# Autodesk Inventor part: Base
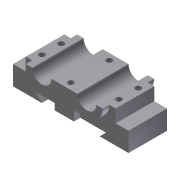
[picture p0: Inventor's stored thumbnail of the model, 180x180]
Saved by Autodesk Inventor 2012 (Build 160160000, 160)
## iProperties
Shininess: 77.0
Length Units: 11269
Angle Units: 11279
Time Units: 11290
Mass Units: 11283
Length Display Precision: 3
Angle Display Precision: 2
Created: 2002-02
Part Number: Base
Document SubType Name: Modeling
Designer: ***
Density: 1 g/cm^3
Material: Default
Density: 0.0
Volumn: 0.0
Area: 0.0
PropertySet Name: Model Information
Control State: 0
Master: False
Checked Out: False
Author: ***
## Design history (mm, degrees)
sketch "Sketch2"
  geometry: L1 (-10.066, -1.263)-(24.934, -1.263); L2 (37.434, 11.237)-(32.434, 11.237); L3 (17.434, 11.237)-(-2.566, 11.237); L4 (-17.566, 11.237)-(-22.566, 11.237); A1 r 12.5 centre (-10.066, 11.237) between (-22.566, 11.237) and (-10.066, -1.263); A2 r 12.5 centre (24.934, 11.237) between (24.934, -1.263) and (37.434, 11.237); A3 r 7.5 centre (24.934, 11.237) between (17.434, 11.237) and (32.434, 11.237); A4 r 7.5 centre (-10.066, 11.237) between (-17.566, 11.237) and (-2.566, 11.237)
  constraints: 8 end point, 8 point on circle, 4 centre point, 3 horizontal, 3 parallel, 2 coincident, 2 equal radius, 2 tangent
  dimensions: "d0" = 12.5 radius of A1; "d1" = 7.5 radius of A4; "d2" = 35 distance of A1.centre A2.centre; "d3" = 12.5 distance between parallel lines of L3 L1
extrude "Extrusion1" new body sketch "Sketch2" stored distance "d4" = 40; taper "d5" = 0 deg
sketch "Sketch4"
  geometry: L1 (-27.566, 1.237)-(-37.566, 1.237); L2 (-37.566, 1.237)-(-37.566, -13.763); L3 (-37.566, -13.763)-(-15.066, -13.763); L4 (-15.066, -13.763)-(-20.066, -8.763); L5 (-20.066, -8.763)-(34.934, -8.763); L6 (34.934, -8.763)-(29.934, -13.763); L7 (29.934, -13.763)-(52.434, -13.763); L8 (52.434, -13.763)-(52.434, 1.237); L9 (52.434, 1.237)-(42.434, 1.237); L10 (24.934, -1.263)-(-10.066, -1.263); L11 (-17.566, 11.237)-(-22.566, 11.237) reference; L12 (37.434, 11.237)-(32.434, 11.237) reference; L13 (-22.566, 11.237)-(-27.566, 11.237); L14 (-27.566, 11.237)-(-27.566, 1.237); L15 (37.434, 11.237)-(42.434, 11.237); L16 (42.434, 11.237)-(42.434, 1.237); A1 r 12.5 centre (24.934, 11.237) between (24.934, -1.263) and (37.434, 11.237); A2 r 12.5 centre (-10.066, 11.237) between (-22.566, 11.237) and (-10.066, -1.263); A3 r 12.5 centre (24.934, 11.237) between (24.934, -1.263) and (37.434, 11.237) reference; A4 r 12.5 centre (-10.066, 11.237) between (-22.566, 11.237) and (-10.066, -1.263) reference
  constraints: 28 end point, 6 perpendicular, 5 equal length, 4 concentric, 4 parallel, 4 point on circle, 2 centre point, 2 collinear, 1 tangent
  dimensions: "d12" = 15 distance of L1.end L2.end; "d13" = 25 distance from line of L3 L11.end; "d14" = 90 distance between parallel lines of L2 L8; "d15" = 5 distance between parallel lines of L5 L7; "d16" = 22.5 distance of L2.end L3.end; "d24" = 5 distance of L12.start L15.end; "d25" = 15 distance from line of L8 L12.start
extrude "Extrusion3" join sketch "Sketch4" stored distance "d17" = 30; taper "d18" = 0 deg
sketch "Sketch5"
  geometry: L1 (-14.934, -1.263)-(0.066, -1.263); L2 (0.066, -1.263)-(0.066, -8.763); L3 (0.066, -8.763)-(-14.934, -8.763); L4 (-14.934, -8.763)-(-14.934, -1.263); L5 (10.066, -1.263)-(-24.934, -1.263) reference; 1 further point
  constraints: 8 end point, 2 parallel, 1 collinear, 1 horizontal, 1 perpendicular
  dimensions: "d19" = 7.5 distance of L1.end L2.end; "d20" = 15 distance of L2.end L3.end; "d21" = 15 distance from line of point (-29.934, -13.763) L4
extrude "Extrusion4" join sketch "Sketch5" distance "d22" = 40; taper "d23" = 0 deg
sketch "Sketch6"
  geometry: L1 (-5, -35)-(0, -35) reference; L2 (-5, -35)-(-5, -5) reference; 1 further point
  dimensions: "d26" = 7.5 distance from line of L1 point (0, -27.5); "d27" = 5 distance from line of L2 point (0, -27.5)
hole "Hole1" sketch "Sketch6" at (0, -27.5) diameter "d28" = 4.5; stored, may be unused: countersink angle "d32" = 82 deg, drill point angle "d34" = 0 deg; dims "d29" = 6, "d30" = 4, "d31" = 2, "d33" = 15
pattern_linear "Rectangular Pattern1" dims "d37" = 60, "d40" = 15
sketch "Sketch7"
  geometry: L1 (-20, -40)-(-20, -35) reference; L2 (0, -40)-(20, -40) reference; 1 further point
  dimensions: "d41" = 30 distance from line of L1 point (10, -35); "d42" = 5 distance from line of L2 point (10, -35)
hole "Hole2" sketch "Sketch7" at (10, -35) diameter "d43" = 4.5; stored, may be unused: countersink angle "d47" = 82 deg, drill point angle "d49" = 0 deg; dims "d44" = 6, "d45" = 4, "d46" = 2, "d48" = 15
pattern_linear "Rectangular Pattern2" dims "d52" = 30
body "Solid1"
